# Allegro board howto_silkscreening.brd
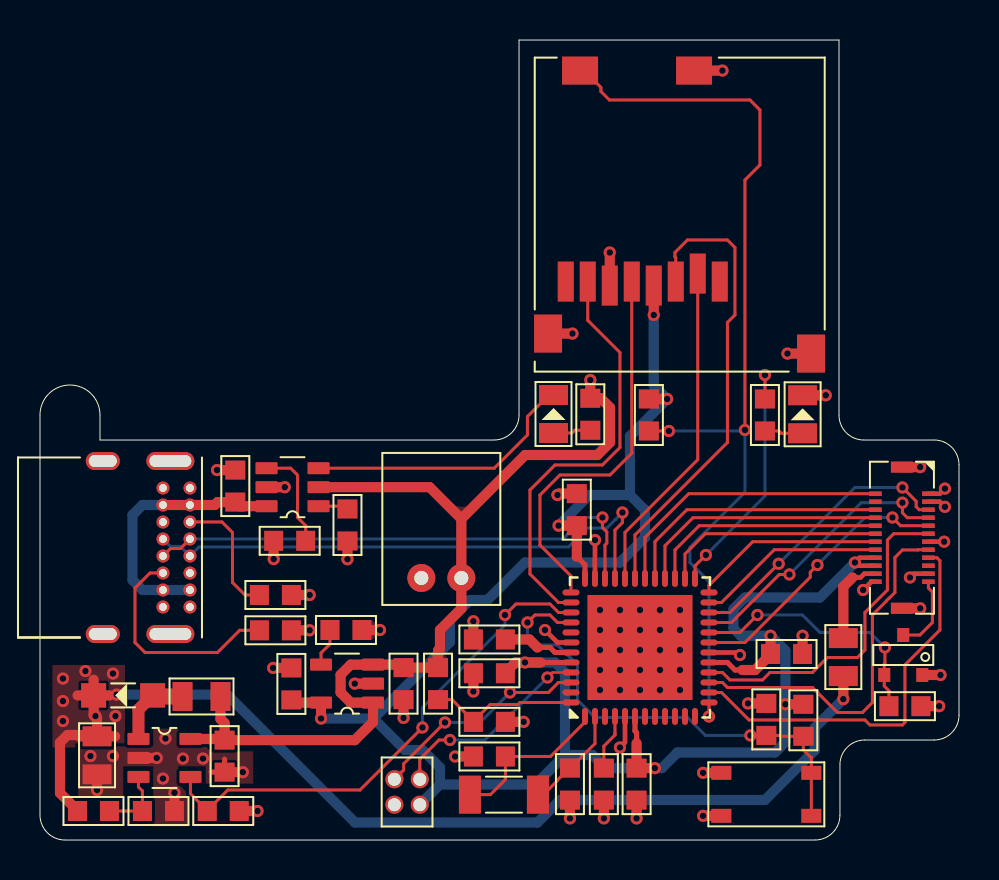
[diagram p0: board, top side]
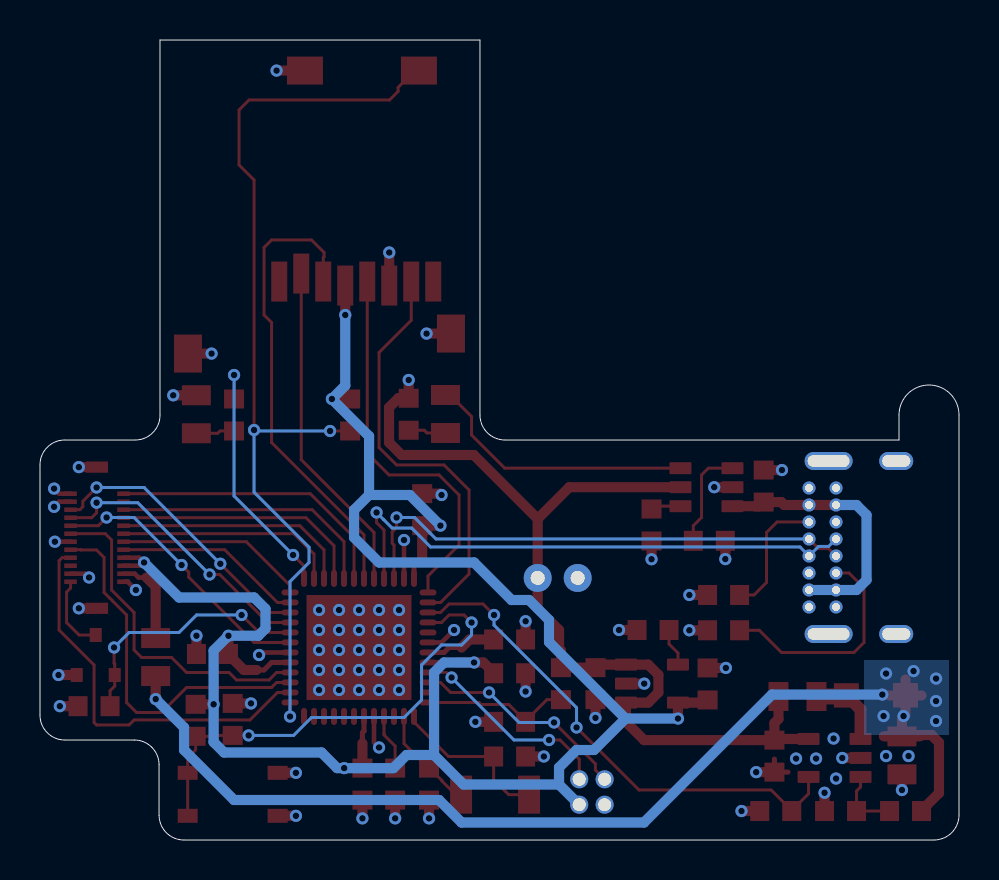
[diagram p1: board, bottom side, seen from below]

Outline 45.95 x 40 mm; copper layers: TOP, L2, L3, BOTTOM. Coordinates in mm from the lower left corner of the outline.
Outline path: 0,21.25 0,1.25 arc(0.37,0.37) 1.25,0 38.76,0 arc(39.64,0.36) 40,1.24 40,3.76 arc(40.36,4.64) 41.24,5 44.71,5 arc(45.59,5.36) 45.95,6.24 45.95,18.76 arc(45.59,19.64) 44.71,20 41.19,20 arc(40.32,20.36) 39.95,21.24 39.95,40 23.95,40 23.95,21.25 arc(23.59,20.37) 22.7,20 3,20 3,21.25 arc(1.5,22.75) 0,21.25

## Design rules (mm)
constraint set DEFAULT: min track width 0.127

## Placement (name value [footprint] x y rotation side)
C15  1uF  [CAP0603]  9.77 17.7 90 top
C16  1uF  [CAP0603]  18.18 7.82 270 top
C19  10uF  [CAP0805]  2.85 4.23 270 top
C20  2.2uF  [CAP0603]  12.57 7.8 90 top
C21  470pF  [CAP0603]  15.3 10.5 0 top
C23  100nF  [CAP0603]  22.47 8.34 180 top
C24  100nF  [CAP0603]  26.84 16.52 90 top
C25  100nF  [CAP0603]  37.33 9.3 0 top
C26  100nF  [CAP0603]  29.83 2.79 270 top
C27  1uF  [CAP0603]  22.47 10.03 180 top
C28  1uF  [CAP0603]  28.2 2.79 270 top
C29  100nF  [CAP0603]  36.32 6.03 90 top
C32  1uF  [CAP0603]  9.23 4.19 270 top
C33  9pF  [CAP0603]  22.47 4.18 180 top
C34  9pF  [CAP0603]  26.5 2.79 270 top
D1  GREEN  [DIO0805]  38.14 21.29 90 top
D2  GREEN  [DIO0805]  25.68 21.3 90 top
D3  SCHOTTKY_DIODE  [SOD-123FL]  4.16 7.23 180 top
J1  -  [USB4085-GF-A]  1.4 14.63 270 top
J2  HEADER VERT 2X2  [2X2-HEADER-50MIL-VERT]  18.36 2.4 270 top
J3  DF37NB-24DS-0.4V  [DF37NB-24DS-0]  43.1 15.11 270 top
J4  2-PIN-CON  [S2B-PH-K]  19.07 13.1 0 top
L1  10uH  [IND0805]  8.08 7.18 180 top
M2  NMOS  [SOT-23-3]  43.17 9.25 0 top
R7  86.6k  [RES0603]  2.67 1.45 0 top
R8  10k  [RES0603]  5.92 1.45 0 top
R9  5.1k  [RES0603]  11.77 12.25 0 top
R10  5.1k  [RES0603]  11.77 10.49 0 top
R11  5.1k  [RES0603]  12.49 14.96 180 top
R12  10k  [RES0603]  38.17 5.99 270 top
R13  10k  [RES0603]  9.16 1.45 0 top
R14  10k  [RES0603]  36.25 21.25 270 top
R15  1.5k  [RES0603]  27.52 21.29 270 top
R16  100k  [RES0603]  19.9 7.82 270 top
R17  100k  [RES0603]  22.47 5.91 0 top
R18  10k  [RES0603]  30.45 21.25 270 top
R19  150R  [RES0805]  40.17 9.15 90 top
R20  10k  [RES0603]  43.25 6.69 0 top
R21  10k  [RES0603]  15.38 15.75 270 top
S1  SPST-NO  [PTS815-SJM-250-SMTR-LFS]  36.32 2.28 0 top
SD2  -  [MEM2061]  30.14 27.92 0 top
U2  BQ21040  [SOT-23-6]  12.63 17.64 180 top
U4  MIC5205-3.3YM5-TR  [SOT-23-5]  15.35 7.82 180 top
U5  AP3012_IC  [SOT-23-5]  6.22 4.1 0 top
U7  ATSAMD21G18A-MF  [48QFN_7X7]  30 9.63 90 top
Y2  32.768 kHz  [2-SMD]  23.2 2.27 0 top

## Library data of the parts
C15 C16 C19-C21 C23-C29 C32-C34 = CAP1: tolerance: 10%
D1 D2 = SML-210MTT86
D3 = SCHOTTKY_DIODE
J1 = USB4085-GF-A
J2 = HEADER VERT 2X2
J3 = DF37NB-24DS-0.4V
J4 = 2-PIN-CON
L1 = IND: tolerance: 20%
M2 = NMOS
R7-R21 = RES1: tolerance: 1%
S1 = PTS815 SJM 250 SMTR LFS
SD2 = MEM2061
U2 = BQ21040
U4 = MIC5205-3.3YM5-TR
U5 = AP3012_IC
U7 = ATSAMD21G18A-MF
Y2 = CC5V-T1A-32.768KHZ-9PF: tolerance: 20%

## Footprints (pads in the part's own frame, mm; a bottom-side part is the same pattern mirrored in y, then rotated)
2-SMD
  rect 1.1x1.9 smd: 1(-1.7,0) 2(1.7,0)
2X2-HEADER-50MIL-VERT
  round 0.9 hole 0.65: 1(-0.635,0.635) 2(-0.635,-0.635) 3(0.635,0.635) 4(0.635,-0.635)
48QFN_7X7
  oval 0.851x0.3 smd: 1(-3.45,2.75) 2(-3.45,2.25) 3(-3.45,1.75) 4(-3.45,1.25) 5(-3.45,0.75) 6(-3.45,0.25) 7(-3.45,-0.25) 8(-3.45,-0.75) 9(-3.45,-1.25) 10(-3.45,-1.75) 11(-3.45,-2.25) 12(-3.45,-2.75) 25(3.45,-2.75) 26(3.45,-2.25) 27(3.45,-1.75) 28(3.45,-1.25) 29(3.45,-0.75) 30(3.45,-0.25) 31(3.45,0.25) 32(3.45,0.75) 33(3.45,1.25) 34(3.45,1.75) 35(3.45,2.25) 36(3.45,2.75)
  oval 0.3x0.851 smd: 13(-2.75,-3.45) 14(-2.25,-3.45) 15(-1.75,-3.45) 16(-1.25,-3.45) 17(-0.75,-3.45) 18(-0.25,-3.45) 19(0.25,-3.45) 20(0.75,-3.45) 21(1.25,-3.45) 22(1.75,-3.45) 23(2.25,-3.45) 24(2.75,-3.45) 37(2.75,3.45) 38(2.25,3.45) 39(1.75,3.45) 40(1.25,3.45) 41(0.75,3.45) 42(0.25,3.45) 43(-0.25,3.45) 44(-0.75,3.45) 45(-1.25,3.45) 46(-1.75,3.45) 47(-2.25,3.45) 48(-2.75,3.45)
  rect 5.25x5.25 smd: 49(0,0)
CAP0603
  rect 0.95x1.001 smd: 1(-0.8,0) 2(0.8,0)
CAP0805
  rrect 1x1.45 smd: 1(-0.95,0) 2(0.95,0)
DF37NB-24DS-0
  rect 0.23x0.63 smd: 1(-2.2,1.325) 2(-2.2,-1.325) 3(-1.8,1.325) 4(-1.8,-1.325) 5(-1.4,1.325) 6(-1.4,-1.325) 7(-1,1.325) 8(-1,-1.325) 9(-0.6,1.325) 10(-0.6,-1.325) 11(-0.2,1.325) 12(-0.2,-1.325) 13(0.2,1.325) 14(0.2,-1.325) 15(0.6,1.325) 16(0.6,-1.325) 17(1,1.325) 18(1,-1.325) 19(1.4,1.325) 20(1.4,-1.325) 21(1.8,1.325) 22(1.8,-1.325) 23(2.2,1.325) 24(2.2,-1.325)
  rect 0.56x1.1 smd: 25(-3.53,0) 26(3.53,0)
DIO0805
  rrect 1x1.45 smd: 1(-0.95,0) 2(0.95,0)
IND0805
  rrect 1x1.45 smd: 1(-0.95,0) 2(0.95,0)
MEM2061
  rect 0.8x2 smd: 1(3.85,0) 2(2.75,0.4) 3(1.65,0) 4(0.55,-0.2) 5(-0.55,0) 6(-1.65,-0.2) 7(-2.75,0) 8(-3.85,0)
  rect 1.4x1.9 smd: P1(-4.735,-2.6) P2(8.415,-3.6)
  rect 1.8x1.4 smd: SW1(-3.135,10.55) SW2(2.565,10.55)
PTS815-SJM-250-SMTR-LFS
  rect 1x0.7 smd: 1(-2.25,1.075) 2(2.25,1.075) 3(-2.25,-1.075) 4(2.25,-1.075)
RES0603
  rect 0.95x1.001 smd: 1(-0.8,0) 2(0.8,0)
RES0805
  rrect 1x1.45 smd: 1(-0.95,0) 2(0.95,0)
S2B-PH-K
  round 1.4 hole 0.7: 1(2,0) 2(0,0)
SOD-123FL
  rect 1.25x1.22 smd: 1(-1.475,0) 2(1.475,0)
SOT-23-3
  rect 0.6x0.7 smd: 1(0.95,-1) 2(0,1) 3(-0.95,-1)
SOT-23-5
  rrect 1.1x0.6 smd: 1(-1.3,0.95) 2(-1.3,0) 3(-1.3,-0.95) 4(1.3,-0.95) 5(1.3,0.95)
SOT-23-6
  rrect 1.1x0.6 smd: 1(-1.3,0.95) 2(-1.3,0) 3(-1.3,-0.95) 4(1.3,-0.95) 5(1.3,0) 6(1.3,0.95)
USB4085-GF-A
  oval 0.9x1.7 hole 0.6x1.4 unplated: (-4.325,1.74) (4.325,1.74)
  round 0.65 hole 0.4: A1(-2.975,6.1) A4(-2.125,6.1) A5(-1.275,6.1) A6(-0.425,6.1) A7(0.425,6.1) A8(1.275,6.1) A9(2.125,6.1) A12(2.975,6.1) B1(2.975,4.75) B4(2.125,4.75) B5(1.275,4.75) B6(0.425,4.75) B7(-0.425,4.75) B8(-1.275,4.75) B9(-2.125,4.75) B12(-2.975,4.75)
  oval 0.9x2.4 hole 0.6x2.1: MNT1(-4.325,5.12) MNT2(4.325,5.12)

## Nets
+3V3: C20.1 C23.1 C24.1 C25.1 C26.1 J2.3 J3.18 J3.20 R12.1 R18.1 SD2.4 U4.5(OUT) U7.6 U7.17 U7.36(VDDIO#36) U7.44
+12V0: C19.1 D3.2 R7.1 R19.1
+VBATT: C16.1 C32.1 J4.1 L1.1 R15.1 R16.1 U2.2 U4.1 U4.3 U5.5(VIN)
+VDDCORE: C27.1 U7.43
GND: C15.2 C16.2 C19.2 C20.2 C21.2 C23.2 C24.2 C25.2 C26.2 C27.2 C28.2 C29.2 C32.2 C33.2 C34.2 D1.2(K) J1.A1 J1.A12 J1.B1 J1.B12 J1.MNT1 J1.MNT2 J2.4 J3.1 J3.3 J3.13 J3.21 J3.24 J3.25 J3.26 J4.2 M2.1(S) R8.2 R9.2 R10.2 R11.2 R13.2 R17.2 R20.2 R21.2 S1.1 S1.3 SD2.6(VSS) SD2.P1 SD2.P2 SD2.SW2 U2.5 U4.2 U5.2 U7.5 U7.18 U7.35 U7.42 U7.49
+V_USB: C15.1 J1.A4 J1.A9 J1.B4 J1.B9(VBUS4) U2.6(VIN)
ADC_VBATT: R16.2 R17.1 U7.48
AREF: C28.1 U7.4
CS*: J3.17 U7.14
D_N: J1.A7 J1.B7 U7.33
D_P: J1.A6 J1.B6 U7.34
DB0: J3.12 U7.26
DB1: J3.11 U7.16
DB2: J3.10 U7.27
DB3: J3.9 U7.19
DB4: J3.8 U7.28
DB5: J3.7 U7.21
DB6: J3.6 U7.29
DB7: J3.5 U7.22
LCD_POWER_EN: R13.1 U5.4 U7.39
LCD_PWM: M2.3 R20.1 U7.20
LCD_RST: J3.2 U7.30
RD*: J3.14 U7.24
RS: J3.16 U7.23
SD_CARD_DETECT: R18.2 SD2.SW1 U7.13
SD_CS: SD2.2 U7.32
SD_MISO: SD2.7 U7.38
SD_MOSI: SD2.3 U7.31
SD_SCK: SD2.5 U7.37
SWCLK: J2.1 U7.45
SWDIO: J2.2 U7.46
WR*: J3.15 U7.15
N42146: J1.A5 R9.1
N42214: R11.1 U2.4
N42218: R21.1 U2.1
N42238: C21.1 U4.4
N42330: J1.B5 R10.1
N42350: D2.1 R15.2
N42414: D2.2(K) U2.3
N42648: D3.1 L1.2 U5.1
N42818: R7.2 R8.1 U5.3
N43960: C33.1 U7.1 Y2.1
N43976: C34.1 U7.2 Y2.2
N44106: C29.1 R12.2 S1.2 S1.4 U7.40
N44702: R14.1 U7.25
N44714: D1.1 R14.2
N46598: J3.22 R19.2
N46734: J3.23 M2.2

Pads without a net: J1 A8 B8; J3 4 19; SD2 1 8; U7 3 7 8 9 10 11 12 41 47

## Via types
v1: diameter 0.61, hole 0.33, TOP to BOTTOM, 118 vias

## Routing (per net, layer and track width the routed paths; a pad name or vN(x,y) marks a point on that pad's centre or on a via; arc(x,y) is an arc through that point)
+3V3: length 107.7
  TOP w0.23: J3.20 40.91,13.71 v1(40.75,13.88) 40.99,14.11 J3.18
  TOP w0.254: U7.36 27.25,13.76 26.84,14.16 ; 25.04,8.88 25.7,8.88 U7.44 ; 29.83,4.83 29.83,5.37 29.75,5.45 U7.6 ; U7.17 34.3,8.88 34.38,8.88 34.75,8.5 35.12,8.5
  TOP w0.508: R18.1 v1(31.36,22.05) ; 35.12,8.5 35.76,8.5 36.53,9.27 C25.1 v1(36.53,10.21) ; 25.04,8.88 v1(24.25,8.88) 23.78,8.88 23.27,8.37 C23.1 ; R12.1 v1(37.27,6.79) ; v1(30.74,3.59) C26.1 29.83,4.83 ; v1(25.93,15.72) C24.1 26.84,14.16 ; C20.1 12.71,6.87 U4.5 v1(14.05,6.07) ; SD2.4 v1(30.69,26.25)
  BOTTOM w0.508: 29.5,17.25 27.46,17.25 v1(25.93,15.72) ; 29.5,17.25 30.25,16.5 30.25,15.13 29,13.88 24.25,13.88 22.38,12 21.5,12 20.5,11 20.5,9.89 16.68,6.07 ; 29.5,17.25 29.5,20.19 v1(31.36,22.05) 30.69,22.72 v1(30.69,26.25) ; 16.68,6.07 v1(14.05,6.07) ; 16.68,6.07 18.25,4.5 19.12,4.5 20,3.63 20,2.78 ; 26.25,4.25 24.77,2.78 20,2.78 ; 26.25,4.25 26.25,8.38 25.75,8.88 v1(24.25,8.88) ; 26.25,4.25 27.62,4.25 28.28,3.59 v1(30.74,3.59) 31.09,3.59 31.88,4.38 36.75,4.38 37.27,4.9 v1(37.27,6.79) 37.27,9.47 v1(36.53,10.21) 35.04,10.21 34.68,10.57 34.68,11.55 35.25,12.13 39,12.13 v1(40.75,13.88) ; 20,2.78 J2.3
+12V0: length 55.5
  TOP w0.508: R7.1 1.87,1.47 1,2.35 1,4.88 1.38,5.25 2.79,5.25 C19.1 ; D3.2 2.68,6.24 2.85,6.07 C19.1 ; D3.2 3.49,7.23 ; D3.2 1.88,7.23 ; D3.2 2.68,8.02 ; C19.1 3.76,5.18 ; C19.1 1.95,5.18 ; R19.1 v1(40.17,7.04)
  BOTTOM w0.508: v1(40.17,7.04) 38.75,5.63 38.75,4.5 36.25,2 26,2 24.88,0.88 15.75,0.88 9.36,7.27 v1(3.83,7.27)
  vias: v1(1.15,8.07) v1(1.15,6.95) v1(1.15,5.95) v1(2.27,8.45) v1(2.77,6.2) v1(3.65,8.32) v1(3.77,6.2)
+VBATT: length 49.2
  TOP w0.508: 21.07,16.06 24.26,19.25 27.88,19.25 28.5,19.88 28.5,21.63 28.04,22.09 R15.1 v1(27.52,23) ; 21.07,16.06 19.48,17.64 U2.2 ; 21.07,16.06 J4.1 21.07,11.57 20,10.5 20,9.57 19.9,9.47 R16.1 C16.1 18.03,8.77 U4.3 15.54,8.77 15.03,8.26 15.03,7.38 15.54,6.87 U4.1 16.65,5.9 15.74,4.99 C32.1 ; U5.5 9.17,5.05 C32.1 ; L1.1 9.03,6.05 9.23,5.85 C32.1
+VDDCORE: length 3.6
  TOP w0.254: U7.43 25.75,9.38 25.5,9.63 24.88,9.63
  TOP w0.508: 24.88,9.63 24.47,10.03 C27.1
GND: length 95.8
  TOP w0.23: U7.18 34.87,9.38 v1(35,9.25) ; v1(41.16,12.5) 41.58,12.91 J3.24 ; v1(29,4.63) 29.25,4.88 U7.5 ; U7.35 v1(27.75,15) ; v1(45.25,17.57) 44.99,17.31 44.42,17.31 ; v1(43.5,13.13) 43.69,13.31 44.42,13.31 ; v1(25.25,10.5) 25.87,9.88 U7.42 ; v1(45.25,16.66) 44.99,16.91 44.42,16.91 ; 44.42,14.91 v1(45.21,14.91)
  TOP w0.254: 9.23,4.05 C32.2 8.55,3.39
  TOP w0.508: J3.25 v1(44.01,18.64) ; SD2.P2 v1(37.38,24.32) ; J3.26 v1(44.01,11.58) ; R21.2 v1(15.38,14.04) ; U2.5 v1(12.24,17.64) ; SD2.P1 v1(26.62,25.32) ; S1.3 v1(33.16,1.21) ; R8.2 v1(6.72,2.36) ; R20.2 v1(44.96,6.69) ; S1.1 v1(33.16,3.36) ; C33.2 v1(20.76,4.18) ; C24.2 25.94,17.32 v1(25.88,17.25) ; C29.2 v1(35.41,6.83) ; 44.12,8.25 v1(45.03,8.25) ; U5.2 v1(5.84,4.1) ; C15.2 v1(8.85,18.5) ; R13.2 v1(10.88,1.45) ; C28.2 v1(28.2,1.08) ; SD2.6 v1(28.49,29.38) ; R9.2 v1(13.48,12.25) ; U4.2 v1(15.74,7.82) ; C21.2 v1(17,10.5) ; C16.2 v1(18.18,6.1) ; R11.2 v1(11.69,14.05) ; C27.2 v1(21.67,10.94) ; SD2.SW2 v1(34.12,38.47) ; C23.2 v1(21.67,7.43) ; R17.2 v1(24.18,5.91) ; C26.2 v1(29.83,1.08) ; C19.2 v1(2.85,2.5) ; C20.2 v1(11.66,8.6) ; R10.2 v1(13.48,10.49) ; C32.2 v1(10.14,3.39) ; D1.2 v1(39.29,22.24) ; C34.2 v1(26.5,1.08) ; C25.2 v1(38.13,10.21)
  L2 w0.508: J1.MNT1 7.9,18.95 ; J1.MNT1 5.14,18.95 ; J1.MNT1 6.52,18.32 ; J1.A1 7.5,18.1 ; J1.A1 7,17.6 ; J1.A1 8,17.6 ; 3.14,10.3 4.17,10.3 ; 3.14,10.3 3.14,9.67 ; 3.14,10.3 3.14,10.93 ; 3.14,10.3 2.11,10.3 ; 3.14,18.32 3.14,18.95 ; 3.14,18.95 4.17,18.95 ; 3.14,18.95 2.11,18.95 ; 19.07,12.22 J4.2 ; J4.2 19.07,13.98 ; J4.2 19.95,13.1 ; J4.2 18.19,13.1 ; 5.65,17.6 J1.B12 ; J1.B12 6.65,17.6 ; J1.B12 6.15,18.1 ; 5.65,11.65 J1.B1 ; J1.B1 6.65,11.65 ; J1.B1 6.15,11.15 ; 5.14,10.3 J1.MNT2 ; J1.MNT2 6.52,9.67 ; J1.MNT2 6.52,10.93 ; J1.MNT2 7.9,10.3 ; 17.72,1.14 J2.4 17.09,1.77 ; 7,11.65 J1.A12 ; J1.A12 7.5,11.15 ; J1.A12 8,11.65
  L3 w0.508: 5.14,18.95 J1.MNT1 ; J1.MNT1 6.52,18.32 ; J1.MNT1 7.9,18.95 ; 6.52,9.67 J1.MNT2 ; J1.MNT2 7.9,10.3 ; J1.MNT2 5.14,10.3 ; J1.MNT2 6.52,10.93 ; J1.A1 8,17.6 ; J1.A1 7,17.6 ; J1.A1 7.5,18.1 ; 3.14,9.67 3.14,10.3 ; 3.14,10.3 4.17,10.3 ; 3.14,10.3 3.14,10.93 ; 3.14,10.3 2.11,10.3 ; 5.65,17.6 J1.B12 ; J1.B12 6.65,17.6 ; J1.B12 6.15,18.1 ; 17.09,1.77 J2.4 17.72,1.14 ; J1.A12 8,11.65 ; J1.A12 7,11.65 ; J1.A12 7.5,11.15 ; 3.14,18.95 4.17,18.95 ; 3.14,18.95 2.11,18.95 ; 3.14,18.95 3.14,18.32 ; 5.65,11.65 J1.B1 ; J1.B1 6.65,11.65 ; J1.B1 6.15,11.15 ; J4.2 19.95,13.1 ; J4.2 18.19,13.1 ; J4.2 19.07,12.22 ; J4.2 19.07,13.98
  vias: v1(2.52,4.2) v1(3.65,4.2) v1(6.15,3.07) v1(6.27,5.07) v1(7.15,4.07) v1(8.15,4.07) v1(28,11.5) v1(28,10.5) v1(28,9.5) v1(28,8.5) v1(28,7.5) v1(29,11.5) v1(29,10.5) v1(29,9.5) v1(29,8.5) v1(29,7.5) v1(30,11.5) v1(30,10.5) v1(30,9.5) v1(30,8.5) v1(30,7.5) v1(31,11.5) v1(31,10.5) v1(31,9.5) v1(31,8.5) v1(31,7.5) v1(32,11.5) v1(32,10.5) v1(32,9.5) v1(32,8.5) v1(32,7.5)
+V_USB: length 13.4
  TOP w0.508: J1.B9 J1.A4 8.74,16.75 8.89,16.9 C15.1 9.97,16.69 U2.6
  BOTTOM w0.508: J1.B9 5.12,16.75 4.62,16.25 4.62,13 5.13,12.5 J1.B4 J1.A9
ADC_VBATT: length 7.5
  TOP w0.15: U7.48 24,6.88 23.9,6.78 22.51,6.78 21.67,5.93 ; R16.2 20.61,7.02 21.67,5.95 21.67,5.93 ; 21.67,5.93 R17.1
AREF: length 2.8
  TOP w0.15: U7.4 28.75,5.33 28.75,5.32 28.75,5.25 28.2,4.7 C28.1
CS*: length 20
  TOP w0.15: 44.42,14.11 44.85,14.11 45,13.96 45,10.5 43.25,8.75 43.25,5.88 43.12,5.75 41.5,5.75 41.25,6 35.46,6 34.08,7.38 U7.14
D_N: length 27.7
  TOP w0.15: v1(29.12,16.38) 29.12,15.87 28.75,15.49 28.75,13.93 28.75,13.93 U7.33
  BOTTOM w0.15: J1.B7 6.52,14.68 7.02,14.68 J1.A7 7.95,14.65 26.42,14.65 27.37,15.6 28.34,15.6 28.77,16.02 v1(29.12,16.38)
D_P: length 26
  TOP w0.15: J1.A6 7.02,14.57 6.52,14.57 J1.B6 ; v1(28.12,16.13) 28.12,15.62 28.34,15.4 28.34,14.84 28.25,14.75 U7.34
  BOTTOM w0.15: J1.A6 26.15,15.05 27.23,16.13 v1(28.12,16.13)
DB0: length 11.2
  TOP w0.15: J3.12 33.27,15.31 32.25,14.3 U7.26
DB1: length 16.7
  TOP w0.15: 44.42,15.31 42.69,15.31 42.38,15 42.38,12.5 41.25,11.38 41.25,9.5 40.88,9.13 39.38,9.13 38.62,8.38 36.5,8.38 36.12,8 34.5,8 34.12,8.38 U7.16
DB2: length 12
  TOP w0.15: U7.27 31.75,14.51 32.96,15.71 J3.10
DB3: length 13.9
  TOP w0.15: v1(42.62,16.13) 43.04,15.71 44.42,15.71 ; U7.19 35.25,9.88 38.52,13.14 38.52,13.39 v1(38.88,13.75)
  BOTTOM w0.15: v1(42.62,16.13) 41.25,16.13 v1(38.88,13.75)
DB4: length 12.7
  TOP w0.15: J3.8 32.65,16.11 31.25,14.71 U7.28
DB5: length 14.1
  TOP w0.15: 44.42,16.11 43.37,16.11 43.12,16.36 v1(43.12,16.87) ; U7.21 34.57,10.88 36.97,13.28 v1(37.47,13.28)
  BOTTOM w0.15: v1(43.12,16.87) 41.06,16.87 v1(37.47,13.28)
DB6: length 13.5
  TOP w0.15: U7.29 30.75,14.92 32.35,16.51 J3.6
DB7: length 14.2
  TOP w0.15: v1(36.94,13.81) 34.5,11.38 U7.22 ; 44.42,16.51 43.96,16.51 43.81,16.66 43.81,16.94 v1(43.12,17.63)
  BOTTOM w0.15: v1(43.12,17.63) 40.75,17.63 v1(36.94,13.81)
LCD_POWER_EN: length 25.6
  TOP w0.15: v1(19.12,5.63) 16,2.5 9.39,2.5 8.36,1.47 ; 8.36,1.47 R13.1 ; 8.36,1.47 7.52,2.31 U5.4 ; U7.39 25.92,11.38 25.5,11.8 23.8,11.8 v1(23.25,11.25)
  BOTTOM w0.15: v1(23.25,11.25) 23.25,10.74 19.12,6.62 v1(19.12,5.63)
LCD_PWM: length 12.9
  TOP w0.15: U7.20 35,10.38 v1(35.88,11.25) ; v1(42.25,9.63) 42.25,8.83 42.22,8.8 M2.3 42.22,7.7 42.45,7.46 R20.1
  BOTTOM w0.15: v1(35.88,11.25) 38.12,11.25 39,10.38 41.5,10.38 v1(42.25,9.63)
LCD_RST: length 14.5
  TOP w0.15: U7.30 30.25,15.13 32.44,17.31 J3.2
RD*: length 9.6
  TOP w0.15: U7.24 33.45,12.73 35.64,14.91 J3.14
RS: length 9.4
  TOP w0.15: J3.16 36.72,14.51 34.08,11.88 U7.23
SD_CARD_DETECT: length 47.6
  TOP w0.15: SD2.SW1 27.21,38.47 28.05,37.63 28.05,37.43 28.48,37 35.5,37 36,36.5 36,33.75 35.25,33 v1(35.25,20.5) ; U7.13 v1(33.45,6.17) ; R18.2 v1(31.45,20.45)
  BOTTOM w0.15: v1(31.45,20.45) 35.2,20.45 v1(35.25,20.5) 35.25,17.39 32.5,14.64 32.5,13.88 33.45,12.92 v1(33.45,6.17)
SD_CS: length 16.8
  TOP w0.15: SD2.2 32.89,19.02 29.25,15.38 U7.32
SD_MISO: length 21.2
  TOP w0.15: SD2.7 27.39,25.99 29,24.38 29,19.63 28.12,18.75 25.75,18.75 24.5,17.5 24.5,13.3 25.92,11.88 U7.38
SD_MOSI: length 23.5
  TOP w0.15: SD2.3 31.79,29.12 31.75,29.16 31.75,29.38 32.38,30 34.38,30 34.75,29.63 34.75,26.25 34.38,25.88 34.38,19.88 29.75,15.25 U7.31
SD_SCK: length 19.6
  TOP w0.15: SD2.5 29.59,19.34 28.5,18.25 26,18.25 25,17.25 25,14.75 26.55,13.2 U7.37
SWCLK: length 10.4
  TOP w0.127: U7.45 25.63,8.38 v1(25.38,8.13)
  TOP w0.15: v1(20.5,5) 19.95,5 18.99,4.04 J2.1
  BOTTOM w0.15: v1(20.5,5) 22.25,5 v1(25.38,8.13)
SWDIO: length 11
  TOP w0.15: U7.46 25.92,7.88 25.42,7.38 v1(23.5,7.38) ; v1(20.25,5.88) 18.18,3.81 18.18,3.5 J2.2
  BOTTOM w0.15: v1(20.25,5.88) 22,5.88 v1(23.5,7.38)
WR*: length 18.6
  TOP w0.15: 44.42,14.51 43.91,14.51 43.89,14.5 43.12,14.5 42.75,14.13 42.75,12.38 42.46,12.09 42.46,12.09 42.32,11.96 42.32,11.95 41.62,11.25 41.62,6.88 41.12,6.38 39.88,6.38 38.63,7.63 34.38,7.63 34.12,7.88 U7.15
N42146: length 6.4
  TOP w0.15: R9.1 10.25,12.25 9.62,12.88 9.62,15.38 9.1,15.9 J1.A5
N42214: length 5.2
  TOP w0.15: R11.1 13.29,15.71 12.88,16.13 12.88,18.25 12.53,18.59 U2.4
N42218: length 1.5
  TOP w0.15: U2.1 15.23,16.69 R21.1
N42238: length 1.9
  TOP w0.15: C21.1 14.5,9.8 14.05,9.35 U4.4
N42330: length 11.3
  TOP w0.15: J1.B5 5.5,13.35 4.75,12.6 4.75,9.88 5.25,9.38 8.88,9.38 9.99,10.49 R10.1
N42350: length 1.9
  TOP w0.15: R15.2 26.74,20.49 26.61,20.35 D2.1
N42414: length 13.8
  TOP w0.15: U2.3 22.72,18.59 24.38,20.25 24.38,21.17 25.45,22.25 D2.2
N42648: length 4
  TOP w0.6: U5.1 4.92,6.52 D3.1
  TOP w0.8: L1.2 5.69,7.18 D3.1
N42818: length 3.4
  TOP w0.15: U5.3 4.92,2.65 5.12,2.45 R8.1 R7.2
N43960: length 8.2
  TOP w0.15: Y2.1 22.52,2.27 23.27,3.02 C33.1 25.53,4.18 27.25,5.9 U7.1
N43976: length 5.3
  TOP w0.15: U7.2 27.75,4.82 26.53,3.59 C34.1 26.47,3.59 25.86,2.98 25.86,2.95 25.17,2.27 Y2.2
N44106: length 24.2
  TOP w0.15: S1.4 S1.2 38.57,4.11 38.17,4.51 R12.2 37.06,5.19 37.02,5.23 C29.1 v1(35.52,5.23) ; U7.40 25.88,10.88 25.5,11.25 24.75,11.25 v1(24.38,10.88)
  BOTTOM w0.15: v1(24.38,10.88) 24.38,10.25 24.88,9.75 25.88,9.75 26.88,8.75 26.88,7 27.75,6.13 32.38,6.13 33.27,5.23 v1(35.52,5.23)
N44702: length 12.8
  TOP w0.15: v1(36.25,23.25) R14.1 ; U7.25 32.75,13.7 v1(33.3,14.25)
  BOTTOM w0.15: v1(36.25,23.25) 36.25,17.2 v1(33.3,14.25)
N44714: length 1.9
  TOP w0.15: R14.2 36.95,20.45 37.07,20.34 D1.1
N46598: length 4.4
  TOP w0.23: J3.22 41.22,13.31 41.03,13.13 40.62,13.13
  TOP w0.508: 40.62,13.13 40.17,12.67 R19.2
N46734: length 3.8
  TOP w0.15: 44.42,12.91 44.42,12.6 44.62,12.4 44.62,10.88 44,10.25 M2.2

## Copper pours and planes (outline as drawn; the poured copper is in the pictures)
+12V0 on TOP: 4.25,8.75 4.25,4.63 0.62,4.63 0.62,8.75
+12V0 on BOTTOM: 0.5,5.25 0.5,9 4.75,9 4.75,5.25
GND on TOP: 1.91,4.69 1.91,2.19 4.16,2.19 4.16,3.69 5.66,3.69 5.66,0.69 7.41,0.69 7.41,2.31 6.91,2.81 6.91,3.69 8.28,3.69 8.28,2.81 10.66,2.81 10.66,4.44 8.53,4.44 8.28,4.69 6.91,4.69 6.91,5.56 5.66,5.56 5.66,4.69
GND on L2, L3: 24.21,39.75 39.7,39.75 39.7,21.24 40.14,20.18 41.19,19.75 44.71,19.75 45.7,18.76 45.7,6.24 44.71,5.25 41.24,5.25 40.18,4.82 39.75,3.76 39.75,1.24 38.76,0.25 1.25,0.25 0.25,1.25 0.25,21.25 2.75,21.25 2.75,19.75 22.7,19.75 23.77,20.19 24.21,21.25

Small or netless copper shapes (teardrops, artwork), in the pictures only: 20 on TOP, 1 on BOTTOM
